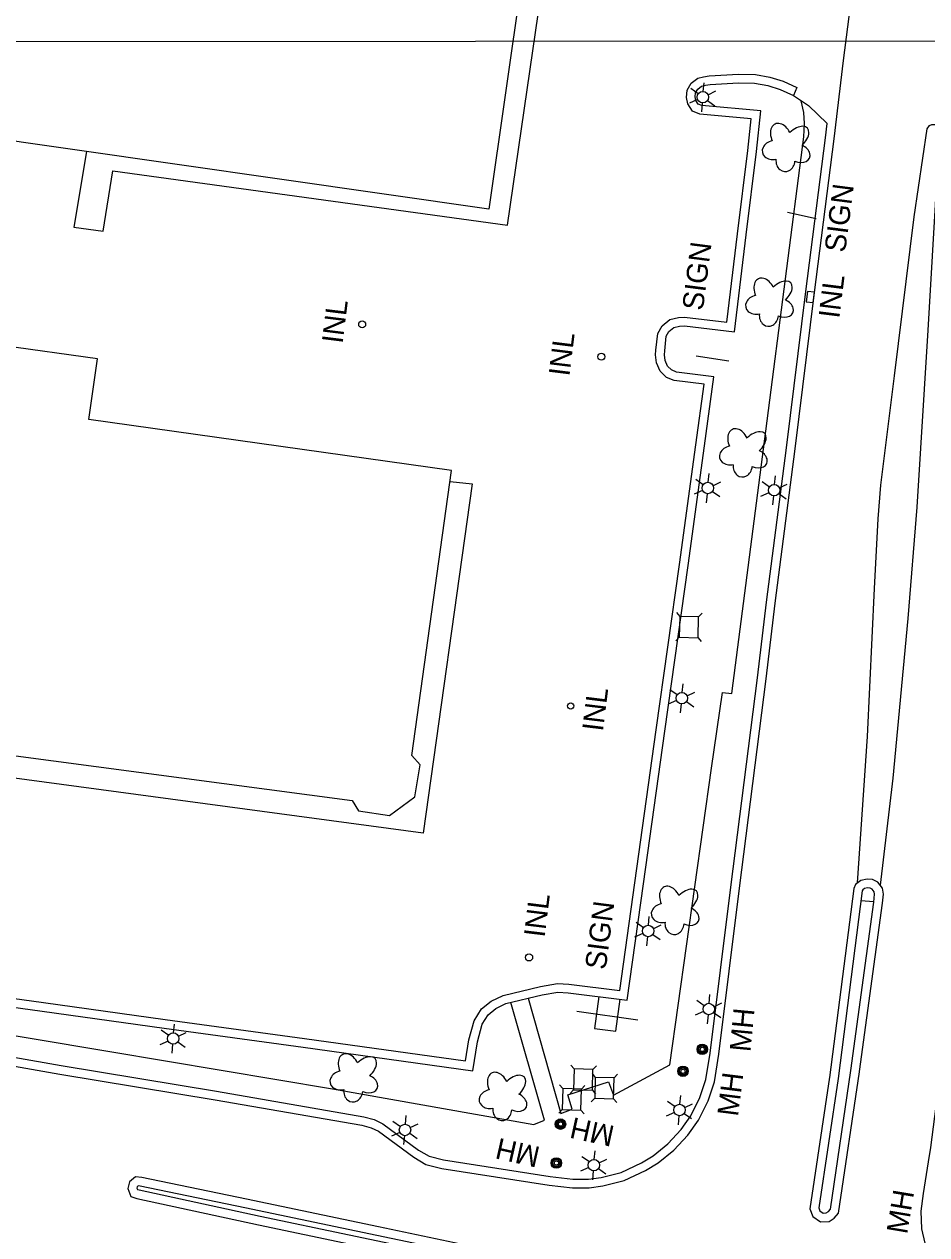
# Model space of a CAD drawing. Extents: x 189384 to 193282, y 256970 to 260388.
# Drawn here: x 190728.8 to 190987.6, y 259169.2 to 259516.4 of the extents above; entities that cross this region are included whole.
import ezdxf

# ---------------------------------------------------------------- set-up
doc = ezdxf.new("R2010")
doc.units = 0
for name, color, linetype in [('E_DRN_Grate', 7, 'Continuous'), ('E_DWY', 7, 'Continuous'), ('E_LAND_Vegetation', 7, 'Continuous'), ('E_MAP_GridLines', 7, 'Continuous'), ('E_MISCPROP', 7, 'Continuous'), ('E_MISCPROP_HvyLine', 7, 'Continuous'), ('E_MISCPROP_Railing', 7, 'Continuous'), ('E_PATH_Sidewalk', 7, 'Continuous'), ('E_RDWY', 7, 'Continuous'), ('E_UTL_AboveGroundPipe', 7, 'Continuous')]:
    doc.layers.add(name, color=color, linetype=linetype)

# ---------------------------------------------------------------- blocks, each defined once
blk = doc.blocks.new('INLT')
at = {"layer": 'E_MISCPROP_Railing'}
blk.add_lwpolyline([(3, -2), (3, 0), (0, 0), (0, -2), (3, -2)], dxfattribs=at)
blk = doc.blocks.new('INL_4')
at = {"layer": 'E_MISCPROP_Railing'}
blk.add_text('INL', height=6, rotation=360, dxfattribs=at).set_placement((-5.79, -2.75))
blk = doc.blocks.new('MHO_10')
at = {"layer": 'E_DRN_Grate'}
for centre, radius in [((0.04, -0.06), 1.5), ((0.04, -0.06), 1.22), ((0.04, -0.07), 0.968), ((0.01, -0.08), 0.605)]:
    blk.add_circle(centre, radius, dxfattribs=at)
blk = doc.blocks.new('MHT_8')
at = {"layer": 'E_DRN_Grate'}
blk.add_text('MH', height=6, rotation=359.9999, dxfattribs=at).set_placement((-5.61, -3.06))
blk = doc.blocks.new('MHO_11')
at = {"layer": 'E_DRN_Grate'}
for centre, radius in [((0.04, -0.06), 1.5), ((0.04, -0.06), 1.22), ((0.04, -0.07), 0.968), ((0.01, -0.08), 0.605)]:
    blk.add_circle(centre, radius, dxfattribs=at)
blk = doc.blocks.new('MHT_9')
at = {"layer": 'E_DRN_Grate'}
blk.add_text('MH', height=6, rotation=360, dxfattribs=at).set_placement((-5.61, -3.06))
blk = doc.blocks.new('MHO_12')
at = {"layer": 'E_DRN_Grate'}
for centre, radius in [((0.04, -0.06), 1.5), ((0.04, -0.06), 1.22), ((0.04, -0.07), 0.968), ((0.01, -0.08), 0.605)]:
    blk.add_circle(centre, radius, dxfattribs=at)
blk = doc.blocks.new('MHT_10')
at = {"layer": 'E_DRN_Grate'}
blk.add_text('MH', height=6, rotation=360, dxfattribs=at).set_placement((-5.61, -3.06))
blk = doc.blocks.new('MHO_13')
at = {"layer": 'E_DRN_Grate'}
for centre, radius in [((0.04, -0.06), 1.5), ((0.04, -0.06), 1.22), ((0.04, -0.07), 0.968), ((0.01, -0.08), 0.605)]:
    blk.add_circle(centre, radius, dxfattribs=at)
blk = doc.blocks.new('MHT_11')
at = {"layer": 'E_DRN_Grate'}
blk.add_text('MH', height=6, rotation=0.0001, dxfattribs=at).set_placement((-5.61, -3.06))
blk = doc.blocks.new('MHT_13')
at = {"layer": 'E_DRN_Grate'}
blk.add_text('MH', height=6, rotation=0.0001, dxfattribs=at).set_placement((-5.61, -3.06))
blk = doc.blocks.new('PED')
at = {"layer": 'E_UTL_AboveGroundPipe'}
for p, q in [((-2.34, 2.71), (-3.29, 3.77)), ((3.06, 2.71), (4.02, 3.77)), ((-3.29, -4.35), (-2.34, -3.29)), ((4.02, -4.35), (3.06, -3.29))]:
    blk.add_line(p, q, dxfattribs=at)
blk.add_lwpolyline([(-2.34, -3.29), (3.06, -3.29), (3.06, 2.71), (-2.34, 2.71)], close=True, dxfattribs=at)
blk = doc.blocks.new('LTP_1')
at = {"layer": 'E_MISCPROP'}
for p, q in [((-0.78, 1.46), (-1.98, 3.76)), ((0.86, 1.37), (2.22, 3.6)), ((-1.61, 0.09), (-4.22, 0.17)), ((1.66, 0), (4.18, -0.07)), ((-0.86, -1.4), (-2.22, -3.59)), ((0.78, -1.44), (2.02, -3.62))]:
    blk.add_line(p, q, dxfattribs=at)
blk.add_circle((0.02, 0.01), 1.64, dxfattribs=at)
blk = doc.blocks.new('TREE')
at = {"layer": 'E_LAND_Vegetation'}
for centre, major_axis, ratio in [((-1.07, 3.38), (0.91, -3.32), 0.782863), ((2.88, 1.66), (-3.52, -1.95), 0.691916), ((-3.74, -0.07), (3.29, -0.08), 0.832022), ((-1.48, -3.66), (1.2, 3.24), 0.716896), ((2.54, -2.64), (-3.34, 3.06), 0.560249)]:
    blk.add_ellipse(centre, major_axis=major_axis, ratio=ratio, start_param=1.570796, end_param=4.712389, dxfattribs=at)
blk = doc.blocks.new('SIGN_3')
at = {"layer": 'E_MISCPROP'}
blk.add_text('SIGN', height=6, rotation=0.0001, dxfattribs=at).set_placement((-9.6, -3.01))
blk = doc.blocks.new('SIGN_5')
at = {"layer": 'E_MISCPROP'}
blk.add_text('SIGN', height=6, rotation=0.0001, dxfattribs=at).set_placement((-9.61, -3.01))

msp = doc.modelspace()

# ---------------------------------------------------------------- linework, layer by layer
at = {"layer": 'E_DWY'}
for points in [[(190746.64, 259479.9), (190743.07, 259458.2), (190751.43, 259457.02), (190754.21, 259474.4), (190867.37, 259458.79), (190877.01, 259525.35), (190893.9, 259522.85), (190895.42, 259531.86), (190748.43, 259553.64)], [(190699.62, 259240.57), (190734.33, 259235.81), (190769.26, 259230.9), (190809.13, 259225.48), (190855.35, 259219.04), (190856.33, 259225.09), (190857.82, 259230.56), (190859.89, 259233.96), (190862.66, 259236.17), (190866.09, 259237.84), (190876.8, 259240.41), (190881.68, 259241.25), (190884.94, 259241.08), (190899.55, 259239.27), (190903.86, 259270.17), (190910.04, 259313.99), (190916.65, 259361.48), (190921.4, 259395.78), (190923.75, 259413.13), (190915.15, 259414.21), (190912.98, 259415.11), (190911.15, 259416.92), (190910.1, 259419.3), (190909.85, 259421.55), (190909.95, 259422.96), (190910.45, 259427.71), (190911.75, 259429.87), (190913.91, 259431.69), (190916.38, 259432.28), (190918.17, 259432.38), (190930.29, 259430.93), (190933.37, 259456.27), (190936.24, 259480.18), (190937.21, 259489.31), (190922.54, 259490.62), (190920.4, 259491.43), (190919.06, 259493.56), (190918.67, 259495.41), (190918.89, 259497.49), (190920.05, 259499.47), (190921.91, 259500.92), (190923.58, 259501.34), (190925.19, 259501.63), (190933.57, 259502.06), (190938.46, 259501.96), (190942.62, 259501.22), (190946.45, 259500.03), (190950.36, 259498.28), (190949.34, 259496)], [(190699.28, 259238.1), (190733.98, 259233.34), (190768.92, 259228.42), (190808.79, 259223), (190857.42, 259216.23), (190858.78, 259224.56), (190860.14, 259229.57), (190861.79, 259232.28), (190864, 259234.04), (190866.94, 259235.47), (190877.31, 259237.96), (190881.83, 259238.74), (190884.73, 259238.59), (190901.68, 259236.48), (190906.34, 259269.82), (190912.52, 259313.65), (190919.13, 259361.13), (190923.88, 259395.44), (190926.57, 259415.29), (190915.79, 259416.65), (190914.39, 259417.23), (190913.25, 259418.36), (190912.54, 259419.96), (190912.36, 259421.61), (190912.44, 259422.75), (190912.88, 259426.89), (190913.68, 259428.23), (190915.07, 259429.39), (190916.74, 259429.8), (190918.09, 259429.87), (190932.48, 259428.15), (190935.85, 259455.97), (190938.73, 259479.89), (190939.97, 259491.58), (190923.1, 259493.08), (190922.07, 259493.48), (190921.41, 259494.51), (190921.19, 259495.54), (190921.32, 259496.69), (190921.96, 259497.79), (190923.03, 259498.63), (190924.1, 259498.89), (190925.48, 259499.14), (190933.61, 259499.56), (190938.21, 259499.47), (190942.02, 259498.79), (190945.57, 259497.69), (190949.34, 259496)], [(190949.34, 259496), (190953.67, 259493.06), (190959.06, 259487.97)], [(190850.91, 259385.28), (190857.2, 259384.55), (190843.24, 259284.34), (190688.25, 259305.24)]]:
    msp.add_lwpolyline(points, dxfattribs=at)
at = {"layer": 'E_MAP_GridLines'}
msp.add_line((190146.34, 259511.09), (191646.33, 259512.15), dxfattribs=at)
msp.add_line((190146.34, 259511.09), (191646.33, 259512.15), dxfattribs=at)
msp.add_line((190146.34, 259511.09), (191646.33, 259512.15), dxfattribs=at)
at = {"layer": 'E_MISCPROP'}
for p, q in [((190947.65, 259462.51), (190955.84, 259460.72)), ((190921.5, 259421.32), (190930.82, 259419.9)), ((190904.75, 259230.69), (190887.23, 259233.2))]:
    msp.add_line(p, q, dxfattribs=at)
at = {"layer": 'E_MISCPROP_HvyLine'}
msp.add_lwpolyline([(190862.07, 259463.38), (190862.07, 259463.38), (190712.55, 259484.77), (190712.55, 259484.77), (190722.01, 259550.92), (190871.53, 259529.52), (190871.53, 259529.52), (190871.53, 259529.52)], close=True, dxfattribs=at)
msp.add_lwpolyline([(190688.16, 259311.6), (190822.79, 259293.76), (190822.79, 259293.76), (190824.64, 259290.78), (190824.64, 259290.78), (190833.5, 259289.42), (190833.5, 259289.42), (190840.76, 259294.84), (190842.32, 259303.93), (190842.32, 259303.93), (190842.32, 259303.93), (190839.91, 259306.64), (190839.91, 259306.64), (190851.35, 259388.44), (190747.34, 259403), (190747.34, 259403), (190749.79, 259420.44), (190749.79, 259420.44), (190722.43, 259424.27)], dxfattribs=at)
at = {"layer": 'E_MISCPROP_Railing'}
for centre, radius in [((190825.71, 259430.3), 0.996), ((190894.29, 259421.05), 1), ((190885.49, 259320.86), 0.908), ((190873.55, 259248.74), 1.03)]:
    msp.add_circle(centre, radius, dxfattribs=at)
at = {"layer": 'E_PATH_Sidewalk'}
for points in [[(190873.31, 259237), (190882.64, 259203.98), (190885.9, 259205.18), (190884.72, 259209.36), (190896.29, 259213.04), (190897.8, 259209.19), (190913.89, 259217.89), (190925.84, 259303.02), (190928.99, 259324.7), (190931.72, 259324.4), (190941.85, 259402.64), (190952.37, 259484.11), (190952.57, 259487.92), (190952.35, 259491.05), (190951.6, 259494.46)], [(190968.73, 259265.09), (190972.42, 259264.74)], [(190661.01, 259237.07), (190707.01, 259229.53), (190753.37, 259221.78), (190817.15, 259211.04), (190874.91, 259200.84), (190878, 259202.02), (190868.29, 259235.8)], [(190893.56, 259237.49), (190892.35, 259228.34), (190898.4, 259227.54), (190899.65, 259236.73)]]:
    msp.add_lwpolyline(points, dxfattribs=at)
at = {"layer": 'E_RDWY'}
for points in [[(191048.1, 259995.99), (191043.46, 259939.63), (191039.72, 259896.92), (191035.9, 259846.97), (191033.06, 259800.26), (191028.66, 259723.54), (191025.78, 259671.21), (191024.1, 259639.83), (191022.83, 259617.71), (191020.45, 259577.04), (191019.17, 259553.9), (191017.17, 259518.52), (191013.34, 259454.66), (191012.18, 259433.77), (191008.14, 259371.5), (191003, 259311.88), (190996.25, 259252.68), (190988.62, 259194.19), (190987.97, 259190.05), (190986.58, 259181.04), (190985.91, 259175.99), (190986.1, 259170.87), (190987.75, 259163.86)], [(190699.93, 259222.12), (190738.97, 259215.27), (190783.56, 259207.89), (190825.62, 259200.59), (190828.3, 259199.89), (190830.34, 259198.87), (190840.51, 259191.41), (190843.93, 259189.35), (190848.55, 259188.23), (190879.31, 259183.4), (190885.98, 259182.66), (190890.79, 259182.65), (190894.68, 259183.17), (190900.83, 259184.71), (190906.97, 259187.58), (190910.61, 259189.78), (190915.04, 259193.46), (190919.06, 259197.77), (190922.13, 259202.02), (190924.87, 259207.6), (190926.7, 259213.08), (190927.98, 259220.95), (190933.92, 259268.59), (190941.57, 259328.63), (190944.16, 259350.3), (190949.81, 259394.6), (190955.37, 259439.46), (190961.05, 259483.56), (190963.74, 259505.98), (190970.14, 259555.94)], [(190699.93, 259222.12), (190738.97, 259215.27), (190783.56, 259207.89), (190825.62, 259200.59), (190828.3, 259199.89), (190830.34, 259198.87), (190840.51, 259191.41), (190843.93, 259189.35), (190848.55, 259188.23), (190879.31, 259183.4), (190885.98, 259182.66), (190890.79, 259182.65), (190894.68, 259183.17), (190900.83, 259184.71), (190906.97, 259187.58), (190910.61, 259189.78), (190915.04, 259193.46), (190919.06, 259197.77), (190922.13, 259202.02), (190924.87, 259207.6), (190926.7, 259213.08), (190927.98, 259220.95), (190933.92, 259268.59), (190941.57, 259328.63), (190944.16, 259350.3), (190949.81, 259394.6), (190955.37, 259439.46), (190961.05, 259483.56), (190963.74, 259505.98), (190970.14, 259555.94)], [(190700.19, 259224.61), (190739.39, 259217.74), (190783.98, 259210.36), (190826.15, 259203.04), (190829.19, 259202.25), (190831.65, 259201.01), (190841.9, 259193.49), (190844.89, 259191.69), (190849.04, 259190.68), (190879.64, 259185.88), (190886.12, 259185.16), (190890.62, 259185.15), (190894.21, 259185.63), (190899.99, 259187.07), (190905.79, 259189.79), (190909.16, 259191.82), (190913.32, 259195.28), (190917.13, 259199.36), (190919.98, 259203.31), (190922.56, 259208.56), (190924.26, 259213.68), (190925.5, 259221.3), (190931.44, 259268.91), (190939.09, 259328.94), (190941.68, 259350.61), (190947.33, 259394.91), (190952.89, 259439.78), (190958.57, 259483.87), (190959.06, 259487.97)], [(190967.7, 259270.09), (190970.55, 259312.1), (190972.64, 259354.58), (190973.63, 259374.5), (190974.42, 259384.22), (190978.37, 259415.58), (190983.96, 259461.15), (190987.69, 259486.37), (190988.35, 259487.34), (190989.07, 259487.66), (190989.94, 259487.65), (190990.58, 259487.35), (190991.03, 259486.65), (190991.23, 259485.88), (190987.89, 259428.62), (190984.7, 259377.84), (190982.15, 259345.94), (190977.85, 259300.18), (190974.19, 259269.46)], [(190968.34, 259215.97), (190974.89, 259264.27), (190975.17, 259266.92), (190974.92, 259268.56), (190973.52, 259270.28), (190972.02, 259271.04), (190970.46, 259271.18), (190968.64, 259270.84), (190967.2, 259269.69), (190966.64, 259268.49), (190959.73, 259214.3)], [(190965.86, 259216.3), (190972.4, 259264.57), (190972.65, 259266.87), (190972.55, 259267.51), (190971.92, 259268.29), (190971.32, 259268.59), (190970.57, 259268.66), (190969.71, 259268.5), (190969.22, 259268.11), (190969.07, 259267.79), (190962.21, 259213.99)], [(190959.74, 259214.36), (190954.03, 259176.62), (190954.89, 259174.37), (190957.15, 259172.86), (190959.56, 259172.95), (190961.07, 259173.92), (190962.33, 259175.41), (190968.33, 259215.94)], [(190962.21, 259213.99), (190956.6, 259176.9), (190956.94, 259176.01), (190957.87, 259175.39), (190958.78, 259175.42), (190959.4, 259175.82), (190959.96, 259176.48), (190965.86, 259216.3)], [(190885, 259158.07), (190870.33, 259163.06), (190830.41, 259171.44), (190792.55, 259179.35), (190762.5, 259185.57), (190760.73, 259185.83), (190759.01, 259184.36), (190758.47, 259182.46), (190759.39, 259180.13), (190761.09, 259179.61), (190795.96, 259172.03), (190846.93, 259161.35), (190853.15, 259159.91), (190883.71, 259149.61)], [(190884.2, 259155.71), (190869.67, 259160.64), (190829.9, 259169), (190792.04, 259176.9), (190762.07, 259183.11), (190761.49, 259183.19), (190761.21, 259182.95), (190761.11, 259182.59), (190761.27, 259182.17), (190761.72, 259182.03), (190796.49, 259174.48), (190847.46, 259163.79), (190853.84, 259162.32), (190884.51, 259151.98)]]:
    msp.add_lwpolyline(points, dxfattribs=at)

# ---------------------------------------------------------------- block references
at = {"layer": 'E_DRN_Grate'}
for name, p, xscale, yscale, rotation in [('MHT_8', (190934.52, 259227.34), 1.0000022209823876, 1.0000022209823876, 84.56074202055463), ('MHO_10', (190923.15, 259222.34), 1.0000022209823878, 1.0000022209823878, 84.5607422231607), ('MHO_13', (190882.58, 259200.85), 1.0000013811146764, 1.0000013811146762, 167.6336227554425), ('MHT_11', (190892.25, 259198.47), 1.0000013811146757, 1.0000013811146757, 167.6336225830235), ('MHT_10', (190870.9, 259192.51), 0.9999983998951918, 0.9999983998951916, 167.2998104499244), ('MHO_12', (190881.41, 259189.69), 0.9999983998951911, 0.9999983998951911, 167.29981026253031)]:
    msp.add_blockref(name, p, dxfattribs=dict(at, xscale=xscale, yscale=yscale, rotation=rotation))
for name, p, rotation in [('MHO_11', (190917.63, 259216.05), 82.81383551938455), ('MHT_9', (190931.13, 259208.89), 82.8138352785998), ('MHT_13', (190979.85, 259175.2), 80.51329720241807)]:
    msp.add_blockref(name, p, dxfattribs=dict(at, rotation=rotation))
at = {"layer": 'E_LAND_Vegetation'}
for p, rotation in [((190947.27, 259481.15), 86.0329750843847), ((190942.5, 259436.78), 86.03297516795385), ((190935.02, 259393.55), 86.03297529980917), ((190915.45, 259262.32), 86.03297564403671), ((190823.32, 259214.28), 86.03297728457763), ((190866.09, 259208.96), 86.03297652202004)]:
    msp.add_blockref('TREE', p, dxfattribs=dict(at, rotation=rotation))
at = {"layer": 'E_MISCPROP'}
for name, p, xscale, yscale, rotation in [('LTP_1', (190923.4, 259495.48), 1.0000014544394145, 1.0000014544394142, 86.27231963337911), ('SIGN_5', (190962.44, 259460.66), 1.000001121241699, 1.000001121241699, 82.62904230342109), ('LTP_1', (190924.81, 259383.35), 1.0000014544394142, 1.0000014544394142, 86.27231960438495), ('LTP_1', (190943.83, 259382.71), 1.0000014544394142, 1.000001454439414, 86.27231926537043), ('LTP_1', (190917.36, 259323.07), 1.0000014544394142, 1.0000014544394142, 86.27231973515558), ('LTP_1', (190907.7, 259256.29), 1.0000014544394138, 1.0000014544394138, 86.27231990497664), ('LTP_1', (190925.09, 259233.9), 1.0000014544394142, 1.0000014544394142, 86.27231959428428), ('LTP_1', (190771.54, 259225.43), 1.0000014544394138, 1.000001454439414, 86.2723223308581), ('LTP_1', (190916.72, 259204.95), 1.000001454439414, 1.0000014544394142, 86.27231974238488), ('LTP_1', (190837.99, 259199.22), 1.000001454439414, 1.0000014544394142, 86.2723211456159), ('LTP_1', (190892.16, 259189.12), 1.0000014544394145, 1.0000014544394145, 86.2723201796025)]:
    msp.add_blockref(name, p, dxfattribs=dict(at, xscale=xscale, yscale=yscale, rotation=rotation))
for p, rotation in [((190921.64, 259444), 82.64383559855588), ((190893.77, 259254.91), 82.6438360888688)]:
    msp.add_blockref('SIGN_3', p, dxfattribs=dict(at, rotation=rotation))
at = {"layer": 'E_MISCPROP_Railing'}
for name, p, xscale, yscale, rotation in [('INL_4', (190960.49, 259437.93), 0.9999984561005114, 0.9999984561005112, 82.92999145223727), ('INL_4', (190818.06, 259430.71), 0.9999984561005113, 0.9999984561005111, 82.92999399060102), ('INLT', (190955.38, 259439.52), 0.9999984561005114, 0.9999984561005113, -97.07000845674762), ('INL_4', (190883.09, 259421.34), 0.9999984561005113, 0.9999984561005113, 82.92999283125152), ('INL_4', (190892.71, 259319.47), 0.9999984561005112, 0.9999984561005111, 82.92999265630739), ('INL_4', (190875.99, 259260.38), 0.9999984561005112, 0.999998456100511, 82.92999295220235)]:
    msp.add_blockref(name, p, dxfattribs=dict(at, xscale=xscale, yscale=yscale, rotation=rotation))
at = {"layer": 'E_UTL_AboveGroundPipe'}
for p, xscale, yscale, rotation in [((190919.76, 259343.2), 0.9999978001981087, 0.9999978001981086, 178.5210779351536), ((190889.46, 259213.38), 0.9999978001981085, 0.9999978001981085, 178.52107847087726), ((190895.52, 259210.96), 0.9999978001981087, 0.9999978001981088, 178.5210783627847), ((190886.18, 259207.73), 0.9999978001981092, 0.9999978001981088, 178.52107852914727)]:
    msp.add_blockref('PED', p, dxfattribs=dict(at, xscale=xscale, yscale=yscale, rotation=rotation))

doc.saveas('drawing.dxf')
